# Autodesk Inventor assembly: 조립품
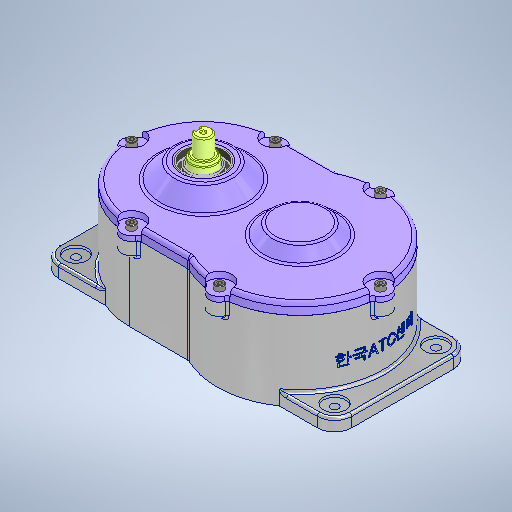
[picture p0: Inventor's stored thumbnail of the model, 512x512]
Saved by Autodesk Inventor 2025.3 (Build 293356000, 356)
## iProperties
Created: 2025-09
Part Number: 조립품
Document SubType Name: Assembly
Designer: PC-15
Author: PC-15
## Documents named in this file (19)
- C:\Users\PC-15\Desktop\750903V1010\조립품.iam
- C:\Users\PC-15\Desktop\750903V1010\본체.ipt
- C:\Users\PC-15\Desktop\750903V1010\6각 구멍붙이 볼트 M4x10\6각 구멍붙이 볼트 M4x10.ipt
- C:\Users\PC-15\Desktop\750903V1010\6각 구멍붙이 볼트 M6x12\6각 구멍붙이 볼트 M6x12.ipt
- C:\Users\PC-15\Desktop\750903V1010\구동 축\구동 축.ipt
- C:\Users\PC-15\Desktop\750903V1010\구동 휠\구동 휠.ipt
- C:\Users\PC-15\Desktop\750903V1010\깊은 홈 볼 베어링 6904\깊은 홈 볼 베어링 6904.ipt
- C:\Users\PC-15\Desktop\750903V1010\스러스트 볼 베어링 51102\스러스트 볼 베어링 51102.ipt
- C:\Users\PC-15\Desktop\750903V1010\스프링 와셔 M3\스프링 와셔 M3.ipt
- C:\Users\PC-15\Desktop\750903V1010\슬롯 축\슬롯 축.ipt
- C:\Users\PC-15\Desktop\750903V1010\슬롯\슬롯.ipt
- C:\Users\PC-15\Desktop\750903V1010\어댑터\어댑터.ipt
- C:\Users\PC-15\Desktop\750903V1010\오일 실 20 35 8\오일 실 20 35 8.ipt
- C:\Users\PC-15\Desktop\750903V1010\육각 너트 M3\육각 너트 M3.ipt
- C:\Users\PC-15\Desktop\750903V1010\칼라\칼라.ipt
- C:\Users\PC-15\Desktop\750903V1010\캠 플로워\캠 플로워.ipt
- C:\Users\PC-15\Desktop\750903V1010\커버\커버.ipt
- C:\Users\PC-15\Desktop\750903V1010\평 와셔 M3\평 와셔 M3.ipt
- C:\Users\PC-15\Desktop\750903V1010\평행 키 6x6x14\평행 키 6x6x14.ipt
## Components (9 placed, 4 different names)
1. 6각 구멍붙이 볼트 M4x10:1
2. 6각 구멍붙이 볼트 M6x12:1
3. 구동 축:1
4. 구동 휠:1 — 각도:2
5. 6각 구멍붙이 볼트 M4x10:2
6. 6각 구멍붙이 볼트 M4x10:3
7. 6각 구멍붙이 볼트 M4x10:4
8. 6각 구멍붙이 볼트 M4x10:5
9. 6각 구멍붙이 볼트 M4x10:6
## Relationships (1: Angle 1)
- 각도:2 [Angle]: 구동 휠:1
